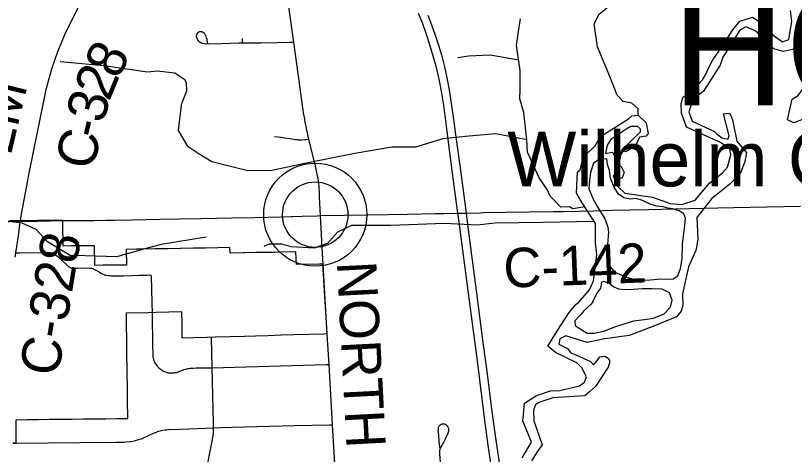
# Model space of a CAD drawing. Extents: x -6.4 to 34, y -4.2 to 22.
# Drawn here: x 3.249 to 4.373, y 19.8 to 20.433 of the extents above; entities that cross this region are included whole.
import ezdxf

# ---------------------------------------------------------------- set-up
doc = ezdxf.new("R2010")
doc.units = 0
for name, color, linetype in [('GM_X_City_Street', 7, 'Continuous'), ('GM_X_Corporation', 7, 'Continuous'), ('GM_X_County_Road', 7, 'Continuous'), ('GM_X_County_Road_Text', 7, 'Continuous'), ('GM_X_Major_River', 7, 'Continuous'), ('GM_X_Minor_River', 7, 'Continuous'), ('GM_X_State_Route', 7, 'Continuous'), ('GM_X_Township_Road', 7, 'Continuous'), ('GM_X_Township_Text', 7, 'Continuous'), ('GM_X_Unincorporated', 7, 'Continuous'), ('GM_X_Unincorporated_Location', 7, 'Continuous'), ('GM_X_Unincorporated_Text', 7, 'Continuous')]:
    doc.layers.add(name, color=color, linetype=linetype)

msp = doc.modelspace()

# ---------------------------------------------------------------- linework, layer by layer
at = {"layer": 'GM_X_City_Street'}
msp.add_lwpolyline([(3.2495, 20.0907), (3.2554, 20.0908), (3.2944, 20.0915), (3.2976, 20.0914), (3.2989, 20.0913), (3.3003, 20.091), (3.3011, 20.0907), (3.3027, 20.0902), (3.3044, 20.0894), (3.3067, 20.088), (3.3087, 20.0865), (3.311, 20.0846), (3.3239, 20.0725), (3.3261, 20.0706), (3.3269, 20.07), (3.3276, 20.0697), (3.3286, 20.0692), (3.3296, 20.0689), (3.3307, 20.0688), (3.3324, 20.0686), (3.3342, 20.0686), (3.3361, 20.0685), (3.3383, 20.0686), (3.351, 20.069), (3.3557, 20.0689), (3.3565, 20.0688), (3.3578, 20.0686), (3.3585, 20.0685), (3.3594, 20.0683), (3.3609, 20.0678), (3.363, 20.0668), (3.3648, 20.0659), (3.371, 20.0622), (3.3728, 20.0612), (3.3755, 20.06), (3.3773, 20.0593), (3.378, 20.0591), (3.3788, 20.0588), (3.3797, 20.0586), (3.3826, 20.0582), (3.3844, 20.058), (3.3857, 20.0579), (3.3877, 20.0578), (3.3897, 20.0577), (3.3929, 20.0577), (3.4047, 20.0578), (3.4279, 20.0586), (3.4389, 20.0588), (3.4418, 20.0589), (3.4431, 20.0587), (3.4442, 20.0583), (3.4446, 20.0576), (3.4448, 20.0566), (3.4457, 20.0189), (3.4461, 20.0038)], dxfattribs=at)
at = {"layer": 'GM_X_Corporation'}
msp.add_lwpolyline([(3.2452, 19.8166), (3.2501, 19.8167), (3.2498, 19.8215), (3.2499, 19.8499), (3.266, 19.8501), (3.2821, 19.8503), (3.2982, 19.8505), (3.3152, 19.8507), (3.3308, 19.8509), (3.3469, 19.8511), (3.363, 19.8512), (3.3791, 19.8513), (3.3962, 19.8515), (3.4111, 19.8516), (3.4107, 19.8787), (3.4106, 19.8891), (3.4104, 19.8986), (3.4102, 19.9135), (3.4101, 19.9194), (3.4101, 19.9199), (3.4097, 19.9479), (3.4096, 19.9575), (3.4095, 19.9621), (3.4095, 19.9662), (3.4092, 19.9852), (3.4089, 20.0041), (3.4403, 20.0048), (3.4517, 20.0051), (3.4886, 20.0059), (3.4889, 19.987), (3.4892, 19.968), (3.506, 19.9685), (3.5257, 19.9691), (3.5371, 19.9694), (3.5588, 19.97), (3.5785, 19.9706), (3.5794, 19.9706), (3.5954, 19.9711), (3.6134, 19.9716), (3.6318, 19.9722), (3.6322, 19.9722), (3.6509, 19.9727), (3.6726, 19.9733), (3.6937, 19.9739), (3.6986, 19.9742), (3.6927, 20.0744), (3.6876, 20.0746), (3.6544, 20.0738), (3.6533, 20.0923), (3.6319, 20.0918), (3.6229, 20.0915), (3.5982, 20.0911), (3.5963, 20.0911), (3.5793, 20.0908), (3.5774, 20.0908), (3.5585, 20.0905), (3.5583, 20.0985), (3.5407, 20.0982), (3.5231, 20.0978), (3.5054, 20.0975), (3.4878, 20.0972), (3.4863, 20.0971), (3.4694, 20.0968), (3.4518, 20.0965), (3.4507, 20.0965), (3.4325, 20.0961), (3.4242, 20.096), (3.4235, 20.0959), (3.4085, 20.0957), (3.4089, 20.0731), (3.3979, 20.073), (3.3869, 20.0729), (3.3752, 20.0728), (3.3634, 20.0727), (3.3629, 20.1011), (3.3515, 20.101), (3.3405, 20.1008), (3.3295, 20.1007), (3.3178, 20.1006), (3.3172, 20.1328), (3.3173, 20.138), (3.2803, 20.1373), (3.261, 20.1371), (3.2557, 20.137), (3.2402, 20.1368)], dxfattribs=at)
at = {"layer": 'GM_X_County_Road'}
for p, q in [((3.6929, 20.0738), (3.6909, 20.106)), ((3.6988, 19.9729), (3.6929, 20.0738))]:
    msp.add_line(p, q, dxfattribs=at)
for points in [[(3.2679, 20.2012), (3.2756, 20.2389), (3.2896, 20.3097), (3.2933, 20.3268), (3.2975, 20.3427), (3.3015, 20.3565), (3.3055, 20.3688), (3.31, 20.3814), (3.3152, 20.3942), (3.3203, 20.406), (3.3308, 20.4276), (3.3441, 20.4541), (3.3671, 20.4994), (3.3781, 20.5199), (3.3969, 20.555), (3.4005, 20.5616), (3.4124, 20.5828), (3.4156, 20.588)], [(3.6876, 20.1795), (3.6873, 20.1832), (3.6872, 20.1854), (3.687, 20.1877), (3.6867, 20.1904), (3.6861, 20.1946), (3.6855, 20.1981), (3.6843, 20.2046), (3.6822, 20.2138), (3.6722, 20.2551), (3.6689, 20.2703), (3.6678, 20.2757), (3.6671, 20.279), (3.6663, 20.2836), (3.6658, 20.2861), (3.6647, 20.2931), (3.6568, 20.3497), (3.6507, 20.3952), (3.6298, 20.5416)], [(3.2559, 20.1364), (3.2571, 20.1439), (3.2599, 20.1597), (3.2666, 20.1953), (3.2679, 20.2012)], [(3.6909, 20.106), (3.6908, 20.108), (3.6894, 20.1357), (3.689, 20.1445), (3.6879, 20.1719), (3.6876, 20.1795)], [(3.8859, 20.148), (3.8869, 20.1481), (3.8992, 20.1483), (3.92, 20.1488), (3.9248, 20.1489), (3.9563, 20.1495), (4.0252, 20.1506), (4.0396, 20.1507), (4.0836, 20.1517), (4.109, 20.1523), (4.1631, 20.1534), (4.2003, 20.1544), (4.2625, 20.1557)], [(4.2625, 20.1557), (4.2856, 20.1562), (4.3818, 20.1581)], [(3.3175, 20.1375), (3.341, 20.1374), (3.362, 20.1376), (3.3793, 20.1378), (3.3925, 20.1381), (3.417, 20.1386), (3.457, 20.1396), (3.4854, 20.14), (3.5168, 20.1406), (3.5609, 20.1415), (3.5945, 20.142), (3.6324, 20.1428), (3.6467, 20.1432)], [(3.6467, 20.1432), (3.6486, 20.1432), (3.6625, 20.1436), (3.6849, 20.1444), (3.689, 20.1445)], [(3.689, 20.1445), (3.7233, 20.145), (3.7555, 20.1455)], [(3.7555, 20.1455), (3.7575, 20.1455), (3.814, 20.1467), (3.855, 20.1474), (3.867, 20.1476), (3.8859, 20.148)], [(3.1632, 20.1353), (3.1896, 20.1359), (3.2147, 20.1362), (3.2404, 20.1362), (3.2559, 20.1364)], [(3.2486, 20.0844), (3.2495, 20.0907), (3.2532, 20.1155), (3.2558, 20.1355), (3.2559, 20.1364)], [(3.2559, 20.1364), (3.2612, 20.1365), (3.2805, 20.1367), (3.3175, 20.1375)], [(3.7195, 19.6228), (3.7178, 19.6496), (3.7155, 19.689), (3.7122, 19.7445), (3.7107, 19.7711), (3.7102, 19.7786), (3.7065, 19.8427), (3.7014, 19.9298), (3.6988, 19.9729)]]:
    msp.add_lwpolyline(points, dxfattribs=at)
at = {"layer": 'GM_X_Major_River'}
for p, q in [((4.1424, 20.053), (4.1492, 20.0516)), ((4.0798, 20.0165), (4.0694, 20.0076))]:
    msp.add_line(p, q, dxfattribs=at)
for points in [[(4.0598, 20.2077), (4.0639, 20.2101), (4.0671, 20.225), (4.073, 20.2334), (4.0856, 20.2454), (4.093, 20.2588), (4.1334, 20.2842), (4.1382, 20.2885), (4.1476, 20.2898), (4.1592, 20.2786), (4.1621, 20.2631), (4.1591, 20.2593), (4.1493, 20.258), (4.1439, 20.2453), (4.1297, 20.2367), (4.1239, 20.2397), (4.1507, 20.2656), (4.151, 20.2694), (4.1472, 20.2731), (4.137, 20.2733), (4.131, 20.2698), (4.1082, 20.2545), (4.1026, 20.2465), (4.1006, 20.2343), (4.1104, 20.236), (4.1147, 20.2273), (4.1141, 20.2194), (4.1228, 20.2157), (4.1275, 20.2067), (4.1247, 20.1991), (4.1198, 20.1975), (4.1155, 20.2046), (4.1114, 20.2022), (4.1173, 20.1876), (4.1281, 20.1768), (4.1683, 20.171), (4.1884, 20.1642), (4.1934, 20.162), (4.2108, 20.1608), (4.23, 20.1669), (4.2504, 20.1915), (4.2694, 20.2063), (4.2764, 20.2144), (4.2814, 20.2323), (4.2797, 20.241), (4.2664, 20.2499), (4.2175, 20.2725), (4.21, 20.2925), (4.2094, 20.3061), (4.2122, 20.3153), (4.2339, 20.3335), (4.2405, 20.3406), (4.246, 20.3504), (4.2475, 20.3546), (4.2551, 20.3695), (4.2673, 20.3868), (4.2843, 20.413), (4.2943, 20.4253), (4.3127, 20.4313), (4.3295, 20.4202), (4.3423, 20.4049), (4.3561, 20.3957), (4.3651, 20.3989), (4.3695, 20.4251), (4.3673, 20.4409)], [(4.3841, 20.3928), (4.3706, 20.3846), (4.3567, 20.3813), (4.3434, 20.3852), (4.3303, 20.3956), (4.3199, 20.4091), (4.3157, 20.4116), (4.3031, 20.4171), (4.2945, 20.4124), (4.2698, 20.3732), (4.2661, 20.3617), (4.242, 20.3242), (4.2267, 20.3117), (4.2209, 20.2946), (4.2257, 20.281), (4.2576, 20.2658), (4.2604, 20.263), (4.2685, 20.2567), (4.2772, 20.255), (4.2787, 20.2596), (4.2709, 20.2913), (4.2792, 20.2926), (4.2816, 20.2881), (4.2835, 20.2828), (4.2901, 20.2522), (4.3041, 20.2354), (4.3016, 20.2228), (4.2951, 20.206), (4.2913, 20.2014), (4.2799, 20.1902), (4.2534, 20.1688), (4.232, 20.1419), (4.2336, 20.1112), (4.2316, 20.0986), (4.2309, 20.0944), (4.22, 20.0707), (4.2116, 20.0315), (4.2119, 20.0152), (4.2094, 20.0064), (4.2027, 19.9983), (4.1689, 19.9844), (4.1347, 19.9716), (4.0966, 19.966), (4.074, 19.9614)], [(4.1492, 20.0516), (4.1655, 20.0519), (4.1798, 20.0533), (4.19, 20.0527), (4.1983, 20.0532), (4.2047, 20.0575), (4.2087, 20.0682), (4.2111, 20.0823), (4.2114, 20.1039), (4.2131, 20.115), (4.2148, 20.1305), (4.2157, 20.1408), (4.2133, 20.1472), (4.2068, 20.1513), (4.1969, 20.1545), (4.1905, 20.1551), (4.1836, 20.1573), (4.1738, 20.1582), (4.165, 20.1611), (4.154, 20.1666), (4.1448, 20.1695), (4.1354, 20.1685), (4.1271, 20.1703), (4.119, 20.1755), (4.1128, 20.1856), (4.1076, 20.1988), (4.1063, 20.2097), (4.1031, 20.2184), (4.1022, 20.2267), (4.0913, 20.2258), (4.083, 20.2203), (4.0787, 20.207), (4.0771, 20.1955), (4.0765, 20.1834), (4.0829, 20.1672), (4.0887, 20.1574), (4.1, 20.1391), (4.1036, 20.1277), (4.1049, 20.1209), (4.1036, 20.1092), (4.1027, 20.0955), (4.1045, 20.0781), (4.1073, 20.0705), (4.1138, 20.0631), (4.1207, 20.0598), (4.1306, 20.0558), (4.1424, 20.053)], [(3.9801, 19.795), (3.9934, 19.8173), (3.9811, 19.8485), (3.9818, 19.8523), (3.9836, 19.874), (4.0009, 19.8849), (4.0212, 19.8914), (4.0344, 19.892), (4.063, 19.8986), (4.0701, 19.904), (4.073, 19.9117), (4.0663, 19.9248), (4.059, 19.9319), (4.0281, 19.9469), (4.017, 19.9562), (4.031, 19.9788), (4.0479, 20.0049), (4.0583, 20.0169), (4.0621, 20.0195), (4.0772, 20.0373), (4.0798, 20.0427), (4.083, 20.0503), (4.0877, 20.088), (4.0862, 20.1054), (4.0861, 20.1331), (4.0635, 20.1684), (4.0585, 20.177), (4.0598, 20.2077)], [(4.0694, 20.0076), (4.0631, 19.9999), (4.0561, 19.9926), (4.0566, 19.9857), (4.0638, 19.9809), (4.0738, 19.9747), (4.084, 19.9749), (4.0979, 19.9778), (4.1137, 19.9841), (4.1257, 19.9878), (4.1415, 19.9926), (4.1566, 19.9944), (4.1698, 19.9965), (4.1852, 20.0029), (4.1941, 20.0125), (4.1966, 20.0225), (4.1927, 20.033), (4.182, 20.0385), (4.1672, 20.039), (4.154, 20.0387), (4.1404, 20.0381), (4.1271, 20.0375), (4.1199, 20.0385), (4.1119, 20.0418), (4.1054, 20.047), (4.0982, 20.0495), (4.0948, 20.0483), (4.0931, 20.0399), (4.0879, 20.0326), (4.082, 20.0207), (4.0798, 20.0165)], [(4.074, 19.9614), (4.0432, 19.9711), (4.0346, 19.9667), (4.0332, 19.9591), (4.0454, 19.9525), (4.0503, 19.9465), (4.0577, 19.9436), (4.079, 19.9338), (4.0829, 19.9289), (4.0888, 19.9359), (4.0922, 19.9405), (4.1001, 19.9418), (4.1047, 19.9381), (4.1067, 19.9339), (4.1045, 19.9259), (4.0861, 19.8979), (4.0775, 19.8901), (4.0708, 19.8843), (4.0244, 19.8815), (4.0041, 19.8748), (3.9996, 19.8713), (3.9967, 19.8636), (3.997, 19.8484), (4.0089, 19.8138), (4.003, 19.8049), (3.9934, 19.7907)]]:
    msp.add_lwpolyline(points, dxfattribs=at)
at = {"layer": 'GM_X_Minor_River'}
for points in [[(4.1476, 20.2898), (4.1475, 20.2989), (4.1383, 20.3067), (4.1257, 20.3091), (4.1172, 20.3185), (4.1077, 20.3429), (4.0888, 20.3881), (4.084, 20.4214), (4.0913, 20.4352), (4.1156, 20.4558), (4.1203, 20.4873), (4.1172, 20.4934)], [(4.0707, 20.1571), (4.0532, 20.1545), (4.0486, 20.1571), (4.0358, 20.1568), (4.0207, 20.1725), (4.0164, 20.1823), (4.0047, 20.1991), (3.9878, 20.236), (3.9868, 20.2538), (3.9827, 20.2936), (3.9766, 20.3132), (3.9771, 20.3273), (3.9774, 20.3542), (3.9722, 20.3901), (3.9739, 20.4031), (3.9742, 20.4073), (3.9776, 20.4289)], [(3.9753, 20.3689), (3.9339, 20.3762), (3.9029, 20.3748), (3.8871, 20.3726)], [(4.4714, 20.2043), (4.462, 20.2038), (4.4528, 20.2108), (4.4523, 20.2366), (4.4457, 20.2444), (4.4412, 20.2462), (4.4397, 20.2424), (4.4286, 20.2308), (4.4199, 20.2292), (4.4073, 20.2354), (4.4002, 20.25), (4.398, 20.272), (4.3963, 20.2818), (4.3872, 20.2843), (4.3721, 20.2787), (4.363, 20.2827), (4.369, 20.3083), (4.3696, 20.3128), (4.3786, 20.3179), (4.3971, 20.3441), (4.3966, 20.3482), (4.4096, 20.3618), (4.4183, 20.3653), (4.4396, 20.3752)], [(3.9868, 20.2538), (3.942, 20.2625), (3.9031, 20.2595), (3.8657, 20.2554), (3.8262, 20.2433), (3.7921, 20.2434), (3.7386, 20.2341), (3.664, 20.2194), (3.6191, 20.2099), (3.584, 20.2092), (3.5323, 20.222), (3.5124, 20.2341), (3.4979, 20.2441), (3.4842, 20.2674), (3.4885, 20.3039), (3.4895, 20.3081), (3.4964, 20.3245), (3.4955, 20.3362), (3.4935, 20.3404), (3.479, 20.35), (3.4536, 20.3529), (3.4392, 20.3515), (3.3763, 20.361), (3.3134, 20.3667)], [(3.524, 20.1133), (3.4591, 20.103), (3.4354, 20.0965), (3.3948, 20.0851), (3.3494, 20.0866), (3.3278, 20.0869), (3.2953, 20.1068), (3.2787, 20.1243), (3.2585, 20.1338), (3.2236, 20.1381), (3.1987, 20.1369), (3.1941, 20.1387), (3.1888, 20.1367), (3.1786, 20.1411)], [(4.0842, 20.136), (4.0587, 20.1358), (4.0101, 20.1344), (3.9405, 20.1335), (3.9152, 20.1307), (3.8682, 20.1333), (3.7904, 20.1303), (3.734, 20.1301), (3.7138, 20.1206), (3.6993, 20.1044), (3.6801, 20.0976), (3.6468, 20.0996), (3.6335, 20.1032), (3.615, 20.1032), (3.6075, 20.1)]]:
    msp.add_lwpolyline(points, dxfattribs=at)
at = {"layer": 'GM_X_State_Route'}
for points in [[(3.83, 20.4368), (3.8361, 20.4218), (3.8416, 20.4066), (3.8465, 20.3918), (3.8514, 20.3751), (3.8558, 20.3588), (3.8597, 20.3418), (3.8631, 20.3243), (3.8659, 20.3069), (3.869, 20.2856), (3.8738, 20.2468), (3.8816, 20.1878), (3.8864, 20.152)], [(3.844, 20.434), (3.8493, 20.4199), (3.8546, 20.4053), (3.8595, 20.3905), (3.8636, 20.3767), (3.8679, 20.3595), (3.8714, 20.3434), (3.8748, 20.3264), (3.8778, 20.3064), (3.8802, 20.2906), (3.8851, 20.2545), (3.89, 20.2169), (3.8958, 20.1735), (3.8992, 20.1483), (3.9008, 20.1354), (3.9072, 20.0876), (3.9136, 20.0366), (3.9226, 19.9685), (3.9295, 19.9159), (3.936, 19.865), (3.9413, 19.827), (3.947, 19.7874)], [(3.8864, 20.152), (3.8869, 20.1481), (3.8882, 20.1384), (3.8891, 20.1315)], [(3.8891, 20.1315), (3.8931, 20.1021), (3.9074, 19.9926), (3.915, 19.9348), (3.9249, 19.8563), (3.9307, 19.8132), (3.9374, 19.7677), (3.9479, 19.704), (3.9557, 19.6586), (3.9635, 19.6165), (3.9731, 19.5677), (3.9816, 19.5269), (3.9974, 19.4566), (4.0056, 19.4228), (4.026, 19.342), (4.0394, 19.2926)]]:
    msp.add_lwpolyline(points, dxfattribs=at)
at = {"layer": 'GM_X_Township_Road'}
msp.add_line((3.2454, 19.8161), (3.2503, 19.8162), dxfattribs=at)
for points in [[(3.5267, 20.3933), (3.5257, 20.3978), (3.5255, 20.3986), (3.5253, 20.3994), (3.5248, 20.401), (3.5241, 20.4029), (3.5235, 20.4044), (3.5231, 20.4052), (3.5226, 20.4061), (3.5222, 20.4067), (3.5216, 20.4075), (3.5204, 20.4086), (3.519, 20.4094), (3.5181, 20.4098), (3.5168, 20.41), (3.5156, 20.4101), (3.5147, 20.41), (3.5134, 20.4096), (3.5121, 20.4086), (3.5109, 20.4075), (3.5102, 20.4062), (3.5099, 20.4049), (3.5098, 20.4034), (3.5101, 20.4019), (3.5105, 20.4007), (3.5112, 20.3993), (3.5118, 20.3984), (3.5127, 20.3973), (3.5137, 20.3963), (3.515, 20.3954), (3.5162, 20.3946), (3.5184, 20.3937), (3.5194, 20.3934), (3.5216, 20.393), (3.524, 20.3927), (3.5464, 20.3931), (3.5713, 20.3939), (3.5763, 20.3939), (3.603, 20.3941), (3.6272, 20.3944), (3.6447, 20.395), (3.6507, 20.3952)], [(3.5763, 20.3939), (3.5764, 20.397), (3.5765, 20.4002)], [(3.6227, 20.2588), (3.6282, 20.2583), (3.632, 20.2578), (3.6376, 20.257), (3.6414, 20.2563), (3.6479, 20.2552), (3.6507, 20.2548), (3.6529, 20.2545), (3.6552, 20.2543), (3.6568, 20.2542), (3.6582, 20.2541), (3.6597, 20.2541), (3.6617, 20.2541), (3.6659, 20.2544), (3.6683, 20.2547), (3.6722, 20.2551)], [(3.4461, 20.0038), (3.4467, 19.9563), (3.4469, 19.9463), (3.4471, 19.9437), (3.4472, 19.9424), (3.4473, 19.9409), (3.4477, 19.9389), (3.448, 19.9376), (3.4483, 19.9365), (3.4486, 19.9356), (3.449, 19.9346), (3.4494, 19.9336), (3.4501, 19.9322), (3.4509, 19.9308), (3.4517, 19.9296), (3.4527, 19.9282), (3.4536, 19.9271), (3.4549, 19.9257), (3.456, 19.9247), (3.458, 19.923), (3.4598, 19.9217), (3.4623, 19.9202), (3.4654, 19.9188), (3.4678, 19.918), (3.4698, 19.9177), (3.4715, 19.9175), (3.4737, 19.9175), (3.4753, 19.9175), (3.4772, 19.9176), (3.4781, 19.9177), (3.4795, 19.9179), (3.4805, 19.918), (3.4814, 19.9182), (3.4827, 19.9186), (3.4835, 19.9188), (3.4847, 19.9193), (3.4856, 19.9196), (3.4868, 19.9201), (3.4886, 19.9208), (3.4901, 19.9215), (3.4921, 19.9222), (3.494, 19.9229), (3.4948, 19.9231), (3.4965, 19.9235), (3.4975, 19.9237), (3.499, 19.9239), (3.5012, 19.9242), (3.5031, 19.9243), (3.5055, 19.9244), (3.5095, 19.9246), (3.5153, 19.9247), (3.5329, 19.9248), (3.6975, 19.9297), (3.7014, 19.9298)], [(3.5234, 19.7726), (3.5328, 19.8189), (3.5341, 19.8264), (3.5343, 19.8283), (3.5345, 19.8302), (3.5346, 19.8319), (3.5347, 19.8336), (3.5347, 19.8355), (3.5347, 19.8382), (3.5347, 19.8451), (3.5329, 19.9248), (3.5316, 19.9679)], [(3.2503, 19.8162), (3.342, 19.8171), (3.3936, 19.8175), (3.3984, 19.8175), (3.4051, 19.8177), (3.4078, 19.8178), (3.4142, 19.8185), (3.4184, 19.8191), (3.4223, 19.8199), (3.4248, 19.8206), (3.4271, 19.8212), (3.4283, 19.8216), (3.4306, 19.8225), (3.4326, 19.8232), (3.4344, 19.824), (3.439, 19.8263), (3.442, 19.8277), (3.4482, 19.8305), (3.4509, 19.8316), (3.4522, 19.8321), (3.453, 19.8324), (3.4545, 19.8329), (3.4558, 19.8333), (3.4578, 19.8339), (3.4594, 19.8343), (3.4615, 19.8347), (3.4654, 19.8353), (3.4675, 19.8355), (3.4696, 19.8356), (3.4869, 19.8364), (3.5347, 19.8382), (3.5455, 19.8386), (3.5615, 19.8391), (3.6518, 19.8415), (3.7027, 19.8426), (3.7065, 19.8427)], [(3.8636, 19.7708), (3.8613, 19.8006), (3.8612, 19.8039), (3.8613, 19.8057), (3.8616, 19.8071), (3.8622, 19.8088), (3.8631, 19.8106), (3.8675, 19.8185), (3.8695, 19.8223), (3.8716, 19.8265), (3.8725, 19.8285), (3.8732, 19.8299), (3.8735, 19.8308), (3.874, 19.8322), (3.8743, 19.8336), (3.8744, 19.8344), (3.8744, 19.8351), (3.8743, 19.836), (3.8741, 19.837), (3.8739, 19.8376), (3.8735, 19.8386), (3.8727, 19.84), (3.8723, 19.8406), (3.8718, 19.8412), (3.8707, 19.8423), (3.8696, 19.843), (3.8686, 19.8434), (3.8676, 19.8436), (3.8668, 19.8436), (3.866, 19.8436), (3.8652, 19.8436), (3.8641, 19.8433), (3.8633, 19.843), (3.8621, 19.8425), (3.8611, 19.8417), (3.8606, 19.8411), (3.8597, 19.84), (3.8593, 19.8392), (3.8589, 19.838), (3.8587, 19.837), (3.8587, 19.8361), (3.8586, 19.835), (3.8586, 19.8338), (3.8587, 19.8327), (3.8597, 19.8195), (3.8599, 19.817), (3.8603, 19.8146), (3.8611, 19.8084)]]:
    msp.add_lwpolyline(points, dxfattribs=at)
at = {"layer": 'GM_X_Unincorporated'}
for radius in [0.0744, 0.0472]:
    msp.add_circle((3.6815, 20.1459), radius, dxfattribs=at)
at = {"layer": 'GM_X_Unincorporated_Location'}
msp.add_line((3.6815, 20.1459), (3.6815, 20.1459), dxfattribs=at)

# ---------------------------------------------------------------- texts
at = {"layer": 'GM_X_County_Road_Text'}
for s, height, rotation, p in [('8', 0.0568, 63.812, (3.3969, 20.3397)), ('2', 0.0568, 67.496, (3.3839, 20.3082)), ('M', 0.0568, 76.3527, (3.2515, 20.2708)), ('3', 0.0568, 76.6832, (3.3765, 20.2765)), ('-', 0.0568, 76.9293, (3.3713, 20.2538)), ('L', 0.0568, 76.6763, (3.2418, 20.2296)), ('C', 0.0568, 76.9729, (3.3608, 20.2084)), ('C-328', 0.05682, 80.6792, (3.3104, 19.9108)), ('C-142', 0.05682, 2.2024, (3.9541, 20.0403)), ('NORTH', 0.05682, 272.9815, (3.7127, 20.0774))]:
    msp.add_text(s, height=height, rotation=rotation, dxfattribs=at).set_placement(p)
at = {"layer": 'GM_X_Township_Text'}
msp.add_text('HOWLAND', height=0.17045, rotation=0, dxfattribs=at).set_placement((4.1959, 20.3037))
at = {"layer": 'GM_X_Unincorporated_Text'}
msp.add_text('Wilhelm Corner', height=0.078977, rotation=0, dxfattribs=at).set_placement((3.9587, 20.1868))

doc.saveas('drawing.dxf')
